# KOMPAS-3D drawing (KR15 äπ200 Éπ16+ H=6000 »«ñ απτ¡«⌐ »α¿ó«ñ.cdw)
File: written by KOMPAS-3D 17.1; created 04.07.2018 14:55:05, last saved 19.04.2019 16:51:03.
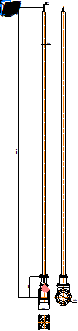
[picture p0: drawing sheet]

Sheet 1: A4, portrait

Title block, sheet 1: name: KR15 Ду200 Ру16+ / H=6000 под ручной привод; material: Внимание! Данный продукт является объектом авторского права ООО «Торговый Дом АДЛ». / Запрещается изменение, копирование, распространение / (в том числе путем копирования на другие сайты и ресурсы в Интернете) / или любое иное использование информации и объектов без предварительного / согласия правообладателя (ООО «Торговый Дом АДЛ»).; mass: 36,7; sheets: 1; organisation: ООО "Торговый дом АДЛ"; sheet format: A4; stored path: \\adlc.lan\data\АДЛ_ПКД\3D-модели\ADL production\Клиновые задвижки серии KR ГРАНАР\Клиновые задвижки KR15 со стационарным удлинением\KOMPAS 2D\KR15 Ду200 Ру16+ H=6000 под ручной привод.cdw

Views: Проекционный вид 6, Проекционный вид 12, Проекционный вид 16
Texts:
  kka
  adl
  УШКЗ.100000.00.00
  Удлинение клиновой задвижки с редуктором
  Крепежное изделие ГОСТ
  Болт
  ГОСТ
  Гайка
  Лит-Масса-Масштаб
  Материал-Предприятие
  Title Specification
  Body Specification ( left align )
  Body Specificaton ( centered )
  Поз.
  Кол.
  Приме-
  чание
  Таблица спецификации
Dimensions and other numbers on the sheet: 6000; 76; 230; 430; 27; 4; 1; 58; 40Х; 019; 1:1; 36,7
